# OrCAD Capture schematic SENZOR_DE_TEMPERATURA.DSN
size A; title: Circuit pentru controlul temperaturii într-o incinta; rev: 1; note: Fagaras Razvan - Vasile, grupa 2123
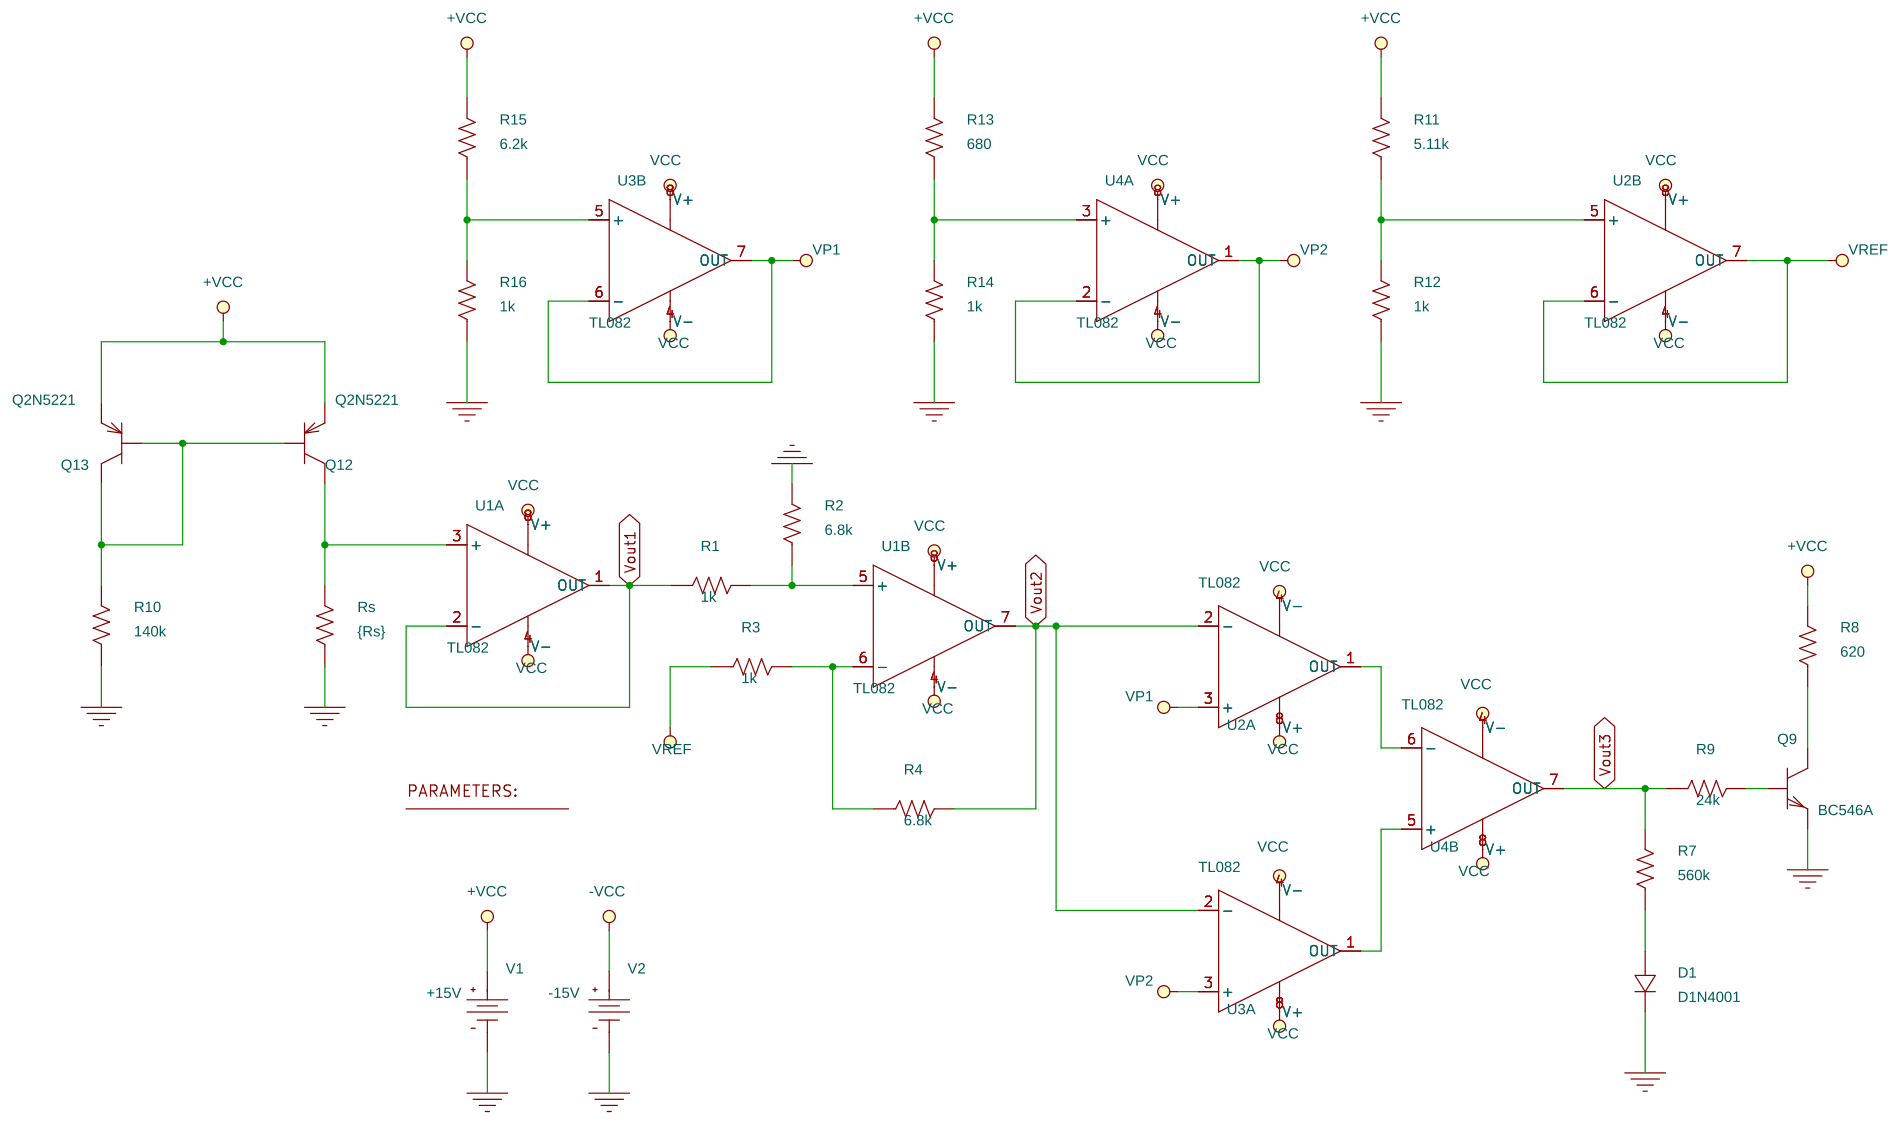
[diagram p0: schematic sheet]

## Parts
1  PARAM
D1  D1N4001  [dax2do41]
Q9  BC546A  [to92]
Q12  Q2N5221  [to92]
Q13  Q2N5221  [to92]
R1  1k  [AXRC05]
R2  6.8k  [AXRC05]
R3  1k  [AXRC05]
R4  6.8k  [AXRC05]
R7  560k  [AXRC05]
R8  620  [AXRC05]
R9  24k  [AXRC05]
R10  140k  [AXRC05]
R11  5.11k  [AXRC05]
R12  1k  [AXRC05]
R13  680  [AXRC05]
R14  1k  [AXRC05]
R15  6.2k  [AXRC05]
R16  1k  [AXRC05]
Rs  {Rs}  [AXRC05]
U1  TL082  [DIP1008W300L450]  (sections A,B)
U2  TL082  [DIP1008W300L450]  (sections A,B)
U3  TL082  [DIP1008W300L450]  (sections A,B)
U4  TL082  [DIP1008W300L450]  (sections A,B)
V1  VDC
V2  VDC

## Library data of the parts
1 = PARAM: Rs: 22k
D1 = D1N4001
Q9 = BC546A
Q12 Q13 = Q2N5221
R1 R3 R4 R7 R9-R12 R14-R16 Rs = R: TOLERANCE: 5%
R2 = R
R8 R13 = R: TOLERANCE: 2%
U1-U4 = TL082
V1 = VDC: DC: +15V
V2 = VDC: DC: -15V

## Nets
+VCC: Q12.1(e) Q13.1(e) R8.2 R11.2 R13.2 R15.2 U1.8(V+) U2.8(V+) U3.8(V+) U4.8(V+) V1.0(+)
-VCC: U1.4(V-) U2.4(V-) U3.4(V-) U4.4(V-) V2.0(+)
0: D1.2 Q9.3(e) R2.2 R10.1 R12.1 R14.1 R16.1 Rs.1 V1.1(-) V2.1(-)
Vout1: R1.1 U1.1(OUT) U1.2(-)
Vout2: R4.2 U1.7(OUT) U2.2(-) U3.2(-)
Vout3: R7.2 R9.1 U4.7(OUT)
Vp1: U2.3(+) U3.6(-) U3.7(OUT)
Vp2: U3.3(+) U4.1(OUT) U4.2(-)
Vref: R3.1 U2.6(-) U2.7(OUT)
N00854: R1.2 R2.1 U1.5(+)
N00858: R3.2 R4.1 U1.6(-)
N01129: D1.1 R7.1
N01320: Q9.1(c) R8.1
N03697: Q9.2(b) R9.2
N04808: Q12.2(b) Q13.2(b) Q13.3(c) R10.2
N04816: Q12.3(c) Rs.2 U1.3(+)
N07121: R11.1 R12.2 U2.5(+)
N07830: R15.1 R16.2 U3.5(+)
N07861: R13.1 R14.2 U4.3(+)
N15215: U2.1(OUT) U4.6(-)
N15227: U3.1(OUT) U4.5(+)
